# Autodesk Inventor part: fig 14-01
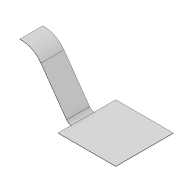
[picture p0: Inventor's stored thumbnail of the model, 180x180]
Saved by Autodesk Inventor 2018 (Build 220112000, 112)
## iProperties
Created: 2017-05
Part Number: fig 14-01
Material: Generic
Document SubType Name: Sheet Metal
Designer: CADCIM 00
Density: 1 g/cm^3
Sheet Metal Rule: Default_mm
Appearance: Default
Author: CADCIM 00
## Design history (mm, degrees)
node "Face1"
  sketch "Sketch1"
    geometry: L1 (0, 0)-(100, 0); L2 (100, 0)-(100, 100); L3 (100, 100)-(0, 100); L4 (0, 100)-(0, 0)
    constraints: 8 end point, 2 parallel, 1 horizontal, 1 perpendicular
    dimensions: "d0" = 100 distance of L3.end L2.end; "d1" = 100 distance of L2.end L1.end
sketch "Sketch5"
  geometry: L1 (-8.558, 4.429)-(-53.165, 67.489); A1 r 10.482 centre (0, 10.482) between (-8.558, 4.429) and (0, 0); A2 r 41.526 centre (-87.066, 43.508) between (-53.165, 67.489) and (-89.447, 84.966)
  constraints: 4 point on circle, 2 centre point, 2 end point, 2 tangent
workplane "Work Plane2"
  workplane "Work Plane1"
node "Contour Flange1"
body "Solid1"
face "Plate1" dims "d2" = 0.5 (= Thickness)
face "Plate3" dims "d2" = 0.5 (= Thickness), "d20" = 0.5 (= BendReliefWidth), "d21" = 0.25 (= BendReliefDepth), "d22" = 1 (= MinimumRemnant), "d23" = 0.5 (= TransitionRadius), "d24" = 10, "d25" = 0, "d26" = 0.5 (= BendRadius), "d27" = 0.5, "d28" = 2 (= CornerReliefSize), "d29" = 0.5 (= GapSize), "d30" = 0.5 (= JacobiRadiusSize), "SeamGap" = 0.01
bend "Bend2" dims "d2" = 0.5 (= Thickness), "d20" = 0.5 (= BendReliefWidth), "d21" = 0.25 (= BendReliefDepth), "d22" = 1 (= MinimumRemnant), "d23" = 0.5 (= TransitionRadius), "d26" = 0.5 (= BendRadius), "d27" = 0.5, "SeamGap" = 0.01
feature "Corner2" dims "d27" = 0.5, "d28" = 2 (= CornerReliefSize), "d29" = 0.5 (= GapSize), "d30" = 0.5 (= JacobiRadiusSize)
other parameters: "Thickness" = 0.5, "BendRadius" = 0.5 (= Thickness), "BendReliefWidth" = 0.5 (= Thickness), "BendReliefDepth" = 0.25 (= 0.5 x Thickness), "CornerReliefSize" = 2 (= 4 x Thickness), "MinimumRemnant" = 1 (= 2 x Thickness), "TransitionRadius" = 0.5 (= BendRadius), "JacobiRadiusSize" = 0.5 (= BendRadius), "GapSize" = 0.5 (= Thickness), "d18" = -23, "d19" = -49.75
